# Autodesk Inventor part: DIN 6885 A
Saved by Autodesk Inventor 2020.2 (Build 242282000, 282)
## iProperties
Manager: www.cadconsulting.pl
Company: Fabian Stasiak CAD Consulting
Created: 2006-02
Part Number: DIN 6885 A
Material: Stal 60
Description: Wpust pryzmatyczny 8x7x28
Vendor: Autodesk Inc.
Document SubType Name: Modeling
Standard: DIN 6885
Designer: F.Stasiak
Standards Organization: DIN
Language: pl-PL
Size Designation: A 8 x 7 x 28
Categories: <MemberInstance Version="R10.0.0"><Categories><Category DisplayName="Części wałów" InternalName="7f7aeb1f-a693-4053-b835-cee3144e0d98" Mnemonic="SHFT"><Category
Stock Number: PFP 3R8728
Project: Przekładnia X51
Density: 7.85 g/cm^3
Appearance: Stal metaliczna (obrabiana_00)
Author: F.Stasiak
Subject: Zbiór ćwiczeń. Autodesk Inventor 2020. Kurs podstawowy
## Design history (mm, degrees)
node "IDS_WORKPLANE{1}"
node "IDS_WORKPLANE{2}"
sketch "Szkic1"
  geometry: L1 (4, 4)-(24, 4); L2 (24, -4)-(4, -4); L3 (0, 10.6)-(0, -6.2) reference; L4 (-2.5, 0)-(32.5, 0) reference; L5 (28, 0)-(28, 7); A1 r 4 centre (4, 0) between (4, 4) and (4, -4); A2 r 4 centre (24, 0) between (24, -4) and (24, 4)
  constraints: 6 end point, 5 point on circle, 4 tangent, 3 point on line, 2 centre point, 1 horizontal, 1 parallel, 1 perpendicular
  dimensions: "d0" = 4 radius of A1 (= 0.5 x PB); "d8" = 4 radius of A2 (= 0.5 x PB); "d9" = 28 distance between parallel lines of L5 L3 (= NLG)
extrude "Bryła1" new body sketch "Szkic1" taper "d3" = 0 deg; stored distance "d4" = 10
node "Bryła2"
node "Korpusy bryłowe"
node "Korpusy powierzchniowe"
other parameters: "d1" = -4 (= -PNT), "d2" = 3 (= PH - PNT), "NLG" = 28 [user parameter; used in 3 equation terms], "PB" = 8 [user parameter; used in 2 equation terms], "PNT" = 4 [user parameter; used in 2 equation terms], "d5" = 0, "d6" = 0, "PH" = 7 [user parameter; used in 1 equation term], "d7" = 0, "WDMIN" = 22 [user parameter], "PUEB" = 3.3 [user parameter], "PLB1" = 28 (= NLG) [user parameter], "PLB2" = 28 (= NLG) [user parameter], "PHH" = 0 [user parameter], "RR" = 0.001 [user parameter]
